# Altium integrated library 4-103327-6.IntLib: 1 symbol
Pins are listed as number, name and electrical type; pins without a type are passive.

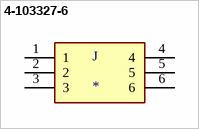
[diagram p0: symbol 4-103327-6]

## 4-103327-6
designator J
6 Position Single Row 2.54 mm Through-Hole Straight AMPMODU Breakaway Header; Centerline_Pitch: 2.54 mm[.1 in]; MF: TE Connectivity; Product_Type: Connector; MP: 4-103327-6; Number_of_Positions: 6
footprint TE_4-103327-6
pins: 1, 2, 3, 4, 5, 6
